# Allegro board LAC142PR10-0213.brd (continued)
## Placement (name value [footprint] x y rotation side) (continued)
CX26  3.3P_0402_50V8C  [C_0402]  18.6 71.45 270 bottom
CX27  3.3P_0402_50V8C  [C_0402]  18.6 64.95 90 bottom
CX28  3.3P_0402_50V8C  [C_0402]  18.6 64.08 270 bottom
CX29  3.3P_0402_50V8C  [C_0402]  18.6 61.26 90 bottom
CX30  3.3P_0402_50V8C  [C_0402]  18.6 60.4 270 bottom
CX49  4.7U_0805_10V4Z  [C_0805]  88.77 151.09 270 top
CX50  0.1U_0402_10V7K  [C_0402]  87.43 151.09 270 top
CX51  4.7U_0805_10V4Z  [C_0805]  83.84 154.13 180 top
CX52  0.1U_0402_10V7K  [C_0402]  85.17 155.55 0 top
CZ1  0.1U_0402_16V4Z  [C_0402]  37.14 64.97 270 top
CZ2  0.1U_0402_16V4Z  [C_0402]  37.27 73.96 90 top
CZ3  10U_0603_6.3V6M  [C_0603]  32.89 73.66 180 top
CZ4  0.1U_0402_16V4Z  [C_0402]  32.9 71.25 180 top
CZ5  0.1U_0402_16V4Z  [C_0402]  41.2 64.97 270 top
CZ6  0.1U_0402_16V4Z  [C_0402]  35.74 64.97 270 top
CZ7  2.2U_0402_6.3V6M  [C_0402]  42.14 67.18 0 top
CZ8  0.1U_0402_16V4Z  [C_0402]  42.14 66.29 0 top
CZ16  0.1U_0402_16V7K  [C_0402]  95.74 90.55 0 bottom
CZ17  0.1U_0402_16V7K  [C_0402]  95.74 89.66 0 bottom
CZ18  10P_0402_50V8J  [C_0402]  25.75 56.73 270 top
CZ19  10P_0402_50V8J  [C_0402]  25.74 58.85 270 top
CZ20  10P_0402_50V8J  [C_0402]  25.75 59.77 90 top
CZ21  10P_0402_50V8J  [C_0402]  23.96 55.86 0 top
CZ22  10P_0402_50V8J  [C_0402]  23.95 57.96 0 top
CZ23  10P_0402_50V8J  [C_0402]  23.98 60.63 0 top
CZ24  10U_0603_6.3V6M  [C_0603]  42.35 64.96 270 top
CZ25  0.1U_0402_16V7K  [C_0402]  88.53 98.17 180 bottom
CZ26  10U_0603_6.3V6M  [C_0603]  32.89 72.39 180 top
CZ27  10P_0402_50V8J  [C_0402]  27.59 55.84 90 top
CZ28  10P_0402_50V8J  [C_0402]  27.55 57.94 90 top
CZ29  10P_0402_50V8J  [C_0402]  27.52 60.68 270 top
CZ30  0.1U_0402_16V7K  [C_0402]  88.53 97.28 180 bottom
CZ31  0.1U_0402_16V7K  [C_0402]  90.73 96.01 180 bottom
CZ32  0.1U_0402_16V7K  [C_0402]  90.73 96.9 180 bottom
CZ33  10P_0402_50V8J  [C_0402]  36 76.44 90 top
CZ34  10P_0402_50V8J  [C_0402]  35.05 76.44 90 top
D3  RB751V-40 SOD-323  [RB751V-40TE17_SOD323-2]  114.07 111.89 90 top
D4  RB751V-40-H-GP  [RB751V-40_SOD323-2]  163.96 42.92 270 top
D20  -  [PESD24VS2UT_SOT23-3]  22.75 77.68 180 top
D31  -  [DB2J31400L_SOD323-2]  55.9 67.94 0 top
D32  -  [DB2J31400L_SOD323-2]  55.9 66.29 0 top
D101  BAS40C-2-GP  [BAS40-04_SOT23-3]  22.22 11.48 90 bottom
D5501  -  [RB551V-30_SOD323-2]  17.67 80.33 270 top
DA8  -  [BAT54C-7-F_SOT23-3]  180.87 24.07 270 bottom
DA13  AZ5125-02S.R7G_SOT23-3  [AZ5125-02SPR7G_SOT23-3]  84.61 9.02 270 top
DA14  AZ5125-02S.R7G_SOT23-3  [AZ5125-02SPR7G_SOT23-3]  84.61 4.32 270 top
DI1  IP4292CZ10-TBR_XSON10_2.5X1~D  [IP4292CZ10-TBR_XSON10_2P5X1]  18.81 37.61 90 bottom
DI2  -  [L30ESDL5V0C3-2_SOT23-3]  19.64 40 90 top
DI3  -  [L30ESDL5V0C3-2_SOT23-3]  189.06 42.42 90 top
DI4  -  [L30ESDL5V0C3-2_SOT23-3]  189.06 38.35 90 top
DX1  -  [RB751V-40_SOD323-2]  94.45 157.02 180 bottom
DX2  -  [PESD5V0U2BT_SOT23-3]  101.4 163.73 0 bottom
EC6104  SCD1U16V2KX-3GP  [C_0402]  26.79 2.69 0 top
FD1  FIDUCAL  [FIDUCIAL_C40M80]  14.24 163.51 0 top
FD2  FIDUCIAL  [FIDUCIAL_C40M80]  14.22 177.8 180 bottom
FD3  FIDUCAL  [FIDUCIAL_C40M80]  200.59 3.05 0 top
FD4  FIDUCIAL  [FIDUCIAL_C40M80]  200.59 3.05 180 bottom
FD5  FIDUCAL  [FIDUCIAL_C40M80]  187.55 23.32 0 top
FD6  FIDUCIAL  [FIDUCIAL_C40M80]  199.65 23 180 bottom
FE1  0.75A_24V_1812L075-24DR~OK  [F_1812L075-24DR]  193.46 130.68 0 top
FX1  1.5A_6V_1206L150PR~D  [F_1206L150PR]  15.67 78.28 90 top
H1  -  [H_3P0]  37.75 164.77 0 top
H2  -  [H_3P0]  20.65 50.77 0 top
H3  -  [H_3P0X3P8N]  6.15 79.07 90 top
H4  -  [H_3P0]  169.65 12.77 0 top
H5  -  [H_3P0]  154.25 60.97 0 top
H6  -  [H_3P2]  199.85 56.27 0 top
H7  -  [H_3P2]  142.05 165.77 0 top
H8  -  [H_4P0N]  148.45 163.97 0 top
H14  -  [H_3P0]  96.65 128.47 0 top
H21  -  [H_3P3]  146.05 150.37 0 top
H22  -  [H_3P3]  200.85 149.17 0 top
H23  -  [H_3P3]  174 112.42 0 top
H31  -  [H_3P4]  118.15 105.07 0 top
H32  -  [H_3P7]  90.95 70.77 0 top
H33  -  [H_3P7]  145.35 70.77 0 top
HDLED1  LED-W-27-GP-U  [LED_12-21C-T3D-CM2P1B18X-2C_3P]  24.45 1.46 0 top
J10  -  [JUMP_43X79]  151.19 129.58 270 top
J11  -  [JUMP_43X118]  151.95 135.72 90 top
J509  -  [JUMP_43X118]  35.74 15.83 90 top
J510  -  [JUMP_43X79]  40.32 15.83 90 top
J511  -  [JUMP_43X118]  30.54 15.83 90 top
JCRT  C-K_80461-5K1-152  [C-K_80461-5K1-152_15P-T-S]  13.8 60.89 90 bottom
JDIMM1  FOX_AS0A621-J4SB-7H  [FOX_AS0A621-J4SB-7H_204P]  88.5 24.97 0 bottom
JDIMM2  FOX_AS0A621-J4RB-7H  [FOX_AS0A621-J4RB-7H_204P]  80.3 38.17 180 bottom
JEDP  ACES-CON40-18-GP  [ACES_51540-04001-P01_40P-T]  80.8 165.93 0 bottom
JFAN  ACES_50224-0030N-001  [ACES_50224-0030N-001_3P-T]  92.46 136.72 25 bottom
JHDD1  ACES_51625-01201-001  [ACES_51625-01201-001_12P-T]  191.4 33.63 270 bottom
JHDD2  ACES_50208-01001-001  [ACES_50208-01001-001_10P]  202.05 27.28 90 bottom
JHDMI  C-K_96067-3K28-192-124  [C-K_96067-3K28-192-124_19P-T]  9.9 60.72 90 bottom
JHDT1  SAMTE_ASP-136446-07-B  [SAMTE_ASP-136446-07-B_20P-T]  48.82 72.64 270 top
JIO1  ACES_51524-0240N-001  [ACES_51524-0240N-001_24P]  191.85 21.76 90 top
JKB  ACES_51510-0304N-P01  [ACES_51510-0304N-P01_30P]  192.05 116.15 270 top
JKBBL  ACES_50524-00401-P01  [ACES_50524-00401-P01_4P]  192.05 121.57 90 top
JLAN  SDAN_601028-008041  [SANTA_130456-661_8P-T]  11.78 167.4 90 bottom
JNGFF  LCN_DAN05-67406-0100  [DAN05-67406-0100_67P-T]  163.37 63.03 270 bottom
JODD  AECS_51519-02001-001  [ACES_51519-02001-001_20P-T]  155.25 76.57 90 top
JP2  -  [JUMP_43X39]  190.42 143.43 0 bottom
JP3  2MM  [JUMP_43X39]  37.6 171.96 180 top
JP7  -  [JUMP_43X79]  153.77 89.66 180 top
JP12  -  [JUMP_43X39]  19.61 10.87 270 bottom
JP13  -  [JUMP_43X79]  189.6 39.58 90 bottom
JP14  -  [JUMP_43X39]  19.61 12.37 90 bottom
JP15  -  [JUMP_43X39]  39.5 74.68 180 top
JPWR  JXT_FP202DH-004M10M  [JXT_FP202DH-004M10M_4P]  197.15 167.79 0 top
JREAD  TAI_PSDATG-11GLBS1NN4H0  [TAI_PSDATG-11GLBS1NN4H0_11P-T]  25.38 10 270 top
JRTC  LOTES_AAA-BAT-054-K01  [LOTES_AAA-BAT-054-K01_2P]  27.15 14.61 180 bottom
JSPK  ACES_50224-0040N-001  [ACES_50224-0040N-001_4P-T]  77.97 5.57 90 bottom
JTP  JXT_FP202DH-008M10M  [JXT_FP202DH-008M10M_8P]  62.58 72.61 90 top
JUSB1  SUYIN_020053GR009M221ZL  [SUYIN_020053GR009M221ZL_9P-T]  14.82 43.47 90 bottom
L22  FBMA-L11-201209-121LMA50T_0805  [KC_FBMA-L11-201209-121LMA50_2P]  147.63 80.51 270 top
LA1  BLM15BB221SN1D_2P  [MURAT_BLM15BB221SN1D_2P]  178.16 9.66 180 bottom
LA3  NBQ160808T-800Y-N 0603  [R_0603]  91.18 5.59 180 top
LA4  NBQ160808T-800Y-N 0603  [R_0603]  91.18 3.3 180 top
LA5  NBQ160808T-800Y-N 0603  [R_0603]  91.18 9.65 180 top
LA6  NBQ160808T-800Y-N 0603  [R_0603]  91.18 7.37 180 top
LA7  0_0402_5%  [R_0402]  192.26 13.31 90 bottom
LA8  0_0603_5%  [R_0603]  191.62 17.4 0 bottom
LA9  0_0603_5%  [R_0603]  191.62 15.88 0 bottom
LA10  0_0402_5%  [R_0402]  189.78 20.65 180 bottom
LE3  FBMA-L11-160808-800LMT_0603  [KC_FBMA-L11-160808-800LMT_2P]  178.56 78.22 270 bottom
LE4  FBMA-L11-160808-800LMT_0603  [KC_FBMA-L11-160808-800LMT_2P]  182.29 82.68 180 top
LED1  LTW-327ZDSKS-5A 3X1 YELLOW/WHITE  [LED_12-22A-S2ST3D-C30-2C_3P]  16.55 2.17 180 top
LI1  S COM FI_ CHILISIN CMMI21T-670Y-N  [MURAT_DLW21SN670HQ2L_4P]  23.39 37.45 180 bottom
LI2  WCM-2012HS-900T_4P  [INPAQ_HCM2012GA900AE_4P]  22.44 41.52 180 top
LI3  S COM FI_ CHILISIN CMMI21T-670Y-N  [MURAT_DLW21SN670HQ2L_4P]  23.39 39.1 180 bottom
LI7  WCM-2012HS-900T_4P  [INPAQ_HCM2012GA900AE_4P]  183.23 42.75 0 top
LI8  WCM-2012HS-900T_4P  [INPAQ_HCM2012GA900AE_4P]  183.23 38.82 0 top
LL1  2.2UH_LQM2MPN2R2NG0L_30%  [MURAT_LQM2MPN2R2NG0L_2P]  55.43 172.12 270 top
LR2  WCM-2012HS-900T_4P  [INPAQ_HCM2012GA900AE_4P]  11.96 18.03 0 bottom
LV2  BLM15BD121SN1D_0402  [R_0402]  169.24 120.11 270 bottom
LV3  BLM15BD121SN1D_0402  [R_0402]  161.36 125.59 0 top
LV4  BLM15BD121SN1D_0402  [R_0402]  164.96 125.91 90 top
LV6  BLM15BB221SN1D_2P  [MURAT_BLM15BB221SN1D_2P]  177.41 136.27 180 top
LV7  BLM15BD121SN1D_0402  [R_0402]  184.61 138.91 180 top
LV8  BLM15BD121SN1D_0402  [R_0402]  184.56 139.91 180 top
LV25  BLM15BD121SN1D_0402  [R_0402]  171.32 134.76 270 top
LV26  BLM15BD121SN1D_0402  [R_0402]  172.2 134.77 270 top
LX1  FBMA-L11-201209-221LMA30T_0805  [KC_FBMA-L11-201209-221LMA30_2P]  83.52 157.77 180 bottom
LX2  WCM-2012HS-900T_4P  [INPAQ_HCM2012GA900AE_4P]  21.48 68.6 180 bottom
LX3  WCM-2012HS-900T_4P  [INPAQ_HCM2012GA900AE_4P]  21.48 72.28 180 bottom
LX4  WCM-2012HS-900T_4P  [INPAQ_HCM2012GA900AE_4P]  21.48 64.92 180 bottom
LX5  WCM-2012HS-900T_4P  [INPAQ_HCM2012GA900AE_4P]  21.48 61.23 180 bottom
LX6  WCM-2012HS-900T_4P  [INPAQ_HCM2012GA900AE_4P]  96.26 160.62 90 bottom
LZ1  SBY100505T-470Y-N_2P  [CHILI_SBY100505T-470Y-N_2P]  24.81 56.73 180 top
LZ2  SBY100505T-470Y-N_2P  [CHILI_SBY100505T-470Y-N_2P]  24.81 58.84 180 top
LZ3  SBY100505T-470Y-N_2P  [CHILI_SBY100505T-470Y-N_2P]  24.83 59.76 180 top
NOREF  -  []  20.65 50.77 0 top
NOREF#2  -  []  142.05 165.77 0 top
NOREF#3  -  []  200.85 149.17 0 top
NOREF#4  -  []  199.85 56.27 0 top
NOREF#5  -  []  37.75 164.77 0 top
NOREF#6  -  []  55.3 220.85 0 top
NOREF#7  -  []  145.35 70.77 0 top
NOREF#8  -  []  90.95 70.77 0 top
NOREF#9  -  []  174 112.42 0 top
NOREF#10  -  []  118.15 105.07 0 top
NOREF#11  -  []  46.26 15.06 0 top
NOREF#12  -  []  146.05 150.37 0 top
NOREF#13  -  []  114.31 8.25 0 top
NOREF#14  -  []  103.05 -41.53 0 top
NOREF#15  -  []  97.47 6.98 0 top
NOREF#16  -  []  134.04 6.67 0 top
NOREF#17  -  []  154.25 60.97 0 top
NOREF#18  -  []  96.65 128.47 0 top
NOREF#19  -  []  169.65 12.77 0 top
NOREF#20  -  []  121.9 61.57 180 bottom
NOREF#21  -  []  117.65 52.1 180 bottom
NOREF#22  -  []  80.94 70.52 180 bottom
PBATT1  SUYIN_200277GR008M270ZR  [SUYIN_200277GR008M270ZR_8P-T]  152.4 179.77 0 bottom
PC1  1000P_0402_50V7K  [C_0402]  83.64 158.08 270 top
PC2  100P_0402_50V8J  [C_0402]  82.75 158.08 270 top
PC3  1000P_0402_50V7K  [C_0402]  76.64 159.56 270 top
PC4  100P_0402_50V8J  [C_0402]  77.53 159.56 270 top
PC5  0.1U_0402_25V6  [C_0402]  141.92 154.19 270 top
PC6  0.1U_0402_25V6  [C_0402]  175.95 83.13 270 top
PC7  0.01U_0402_25V7K  [C_0402]  155.17 177.67 0 top
PC8  1000P_0402_50V7K  [C_0402]  158.12 177.67 180 top
PC13  .1U_0402_16V7K  [C_0402]  179.89 67.39 270 bottom
PC14  .1U_0402_16V7K  [C_0402]  146.36 170.89 270 top
PC15  0.01U_0402_25V7K  [C_0402]  149.99 168.15 180 top
PC16  .1U_0402_16V7K  [C_0402]  147.76 160.86 270 top
PC100  4.7U_0603_6.3V6K  [C_0603]  48.13 53.4 0 top
PC101  150U_D2_6.3VY_R15M  [C_D2]  29.27 31.73 90 bottom
PC102  100P_0402_50V8J  [C_0402]  39.86 54.23 0 top
PC103  680P_0402_50V7K  [C_0402]  34.59 44.07 0 bottom
PC104  0.1U_0603_25V7K  [C_0603]  38.22 51.18 180 top
PC105  1U_0603_25V6K  [C_0603]  41.29 47.27 180 top
PC106  1U_0603_10V6K  [C_0603]  42.39 47.27 0 top
PC107  150U_D2_6.3VY_R15M  [C_D2]  49.21 31.75 90 bottom
PC108  100P_0402_50V8J  [C_0402]  43.05 54.23 0 top
PC109  1U_0603_10V6K  [C_0603]  41.9 54.23 90 top
PC110  0.1U_0603_25V7K  [C_0603]  47.3 51.12 180 top
PC111  680P_0402_50V7K  [C_0402]  42.36 44.01 180 bottom
PC112  10U_0805_25V6K  [C_0805]  40.36 45.25 270 top
PC113  0.1U_0402_25V6  [C_0402]  39.04 44.94 270 top
PC114  2200P_0402_50V7K  [C_0402]  38.15 44.94 270 top
PC115  10U_0805_25V6K  [C_0805]  36.84 45.27 270 top
PC200  0.1U_0603_25V7K  [C_0603]  64.89 18.92 180 top
PC201  2200P_0402_50V7K  [C_0402]  70 25.15 180 bottom
PC202  0.1U_0402_10V7K  [C_0402]  57.28 21.97 180 top
PC203  0.1U_0402_10V7K  [C_0402]  57.28 22.86 180 top
PC204  1U_0603_10V6K  [C_0603]  59.75 16.45 90 top
PC205  10U_0805_6.3V6K  [C_0805]  65.08 24.64 0 top
PC206  10U_0805_25V6K  [C_0805]  70.39 22.86 180 bottom
PC207  680P_0402_50V7K  [C_0402]  74.67 13.92 270 bottom
PC208  0.1U_0402_25V6  [C_0402]  70 24.19 180 bottom
PC209  1U_0603_10V6K  [C_0603]  57.4 19.05 180 top
PC210  0.033U_0402_16V7K  [C_0402]  60.06 24.76 90 top
PC211  10U_0805_6.3V6K  [C_0805]  65.08 22.86 0 top
PC212  10U_0805_25V6K  [C_0805]  70.39 21.08 180 bottom
PC213  220U_D2_2VY_R15M  [C_D2]  76.41 24.76 180 top
PC214  220P_0402_25V8J  [C_0402]  58.22 24.76 0 top
PC301  0.1U_0402_16V7K  [C_0402]  134.54 148.65 0 bottom
PC302  0.1U_0402_25V6  [C_0402]  140.39 142.05 90 top
PC303  2200P_0402_50V7K  [C_0402]  141.34 142.05 90 top
PC304  10U_0805_25V6K  [C_0805]  144.52 141.41 90 top
PC305  0.1U_0603_25V7K  [C_0603]  141.28 148.65 180 top
PC306  1U_0603_10V6K  [C_0603]  139.88 147.38 0 top
PC307  220U_D2_2VY_R15M  [C_D2]  135.44 126.05 0 top
PC308  10U_0805_25V6K  [C_0805]  142.74 141.41 90 top
PC309  680P_0402_50V7K  [C_0402]  136.07 141.27 90 bottom
PC310  220U_D2_2VY_R15M  [C_D2]  135.03 123.32 0 bottom
PC401  0.1U_0402_16V7K  [C_0402]  32.7 3.89 270 top
PC402  1U_0402_6.3V6K  [C_0402]  195.83 132.6 270 bottom
PC403  4.7U_0603_6.3V6K  [C_0603]  32.76 7.75 180 top
PC404  0.01U_0402_25V7K  [C_0402]  42.3 5.21 180 top
PC405  22UF_0805_6.3V6M  [C_0805]  42.09 7.91 90 top
PC501  0.1U_0402_25V6K  [C_0402]  59.49 32.44 90 bottom
PC502  1U_0603_10V6K  [C_0603]  58.9 38.67 270 bottom
PC503  1U_0603_10V6K  [C_0603]  57.67 38.68 270 bottom
PC504  10U_0805_25V6K  [C_0805]  68.92 46.9 270 top
PC505  10U_0805_25V6K  [C_0805]  63.3 45.94 270 top
PC506  10U_0805_25V6K  [C_0805]  65.08 45.94 270 top
PC507  2200P_0402_50V7K  [C_0402]  72.07 46.18 270 top
PC508  0.1U_0402_25V6  [C_0402]  71.18 46.18 270 top
PC509  1000P_0402_50V7K  [C_0402]  61.27 33.35 270 bottom
PC510  0.22U_0603_25V7K  [C_0603]  61.97 40.39 180 top
PC511  680P_0603_50V7K  [C_0603]  72.89 46.1 270 bottom
PC512  1000P_0402_50V7K  [C_0402]  67.18 30.75 270 top
PC513  150P_0402_50V8J  [C_0402]  64.46 37.15 180 bottom
PC514  330P_0402_50V7K  [C_0402]  68.18 31.62 0 top
PC515  390P_0402_50V7K  [C_0402]  68.33 37.08 180 top
PC516  0.022U_0402_25V7K  [C_0402]  64.7 34.56 270 top
PC517  0.1U_0603_16V7K  [C_0603]  64.95 30.8 90 bottom
PC518  330P_0402_50V  [C_0402]  68.18 32.51 0 top
PC519  0.1U_0603_50V7K  [C_0603]  67.81 38.42 90 top
PC520  820P_0402_50V7K  [C_0402]  65.59 34.65 180 bottom
PC521  0.01U_0402_50V7K  [C_0402]  62.17 35.94 180 bottom
PC522  0.1U_0402_25V6  [C_0402]  70.29 46.18 270 top
PC523  1000P_0402_50V7K  [C_0402]  54.67 31.42 90 top
PC601  0.1U_0402_16V7K  [C_0402]  159.19 44.53 270 bottom
PC602  22UF_0805_6.3V6M  [C_0805]  156.86 40.64 180 bottom
PC603  68P_0402_50V8J  [C_0402]  158.3 40.06 90 bottom
PC604  22UF_0805_6.3V6M  [C_0805]  152.86 49.34 180 bottom
PC605  22UF_0805_6.3V6M  [C_0805]  152.86 47.56 180 bottom
PC606  680P_0402_50V7K  [C_0402]  154.41 43.69 0 bottom
PC705  2200P_0402_25V7K  [C_0402]  130.09 171.13 0 bottom
PC708  0.1U_0402_25V6  [C_0402]  121.12 173.43 270 bottom
PC711  0.01UF_0402_25V7K  [C_0402]  80.97 170.97 180 top
PC721  0.22U_0603_25V7K  [C_0603]  123.06 166.62 180 bottom
PC742  5600P_0402_25V7K  [C_0402]  78.52 164.47 180 top
PC744  0.1U_0402_25V6  [C_0402]  78.52 166.5 180 top
PC745  0.1U_0402_25V6  [C_0402]  112.5 163.58 0 top
PC746  0.1U_0402_25V6  [C_0402]  112.5 164.47 0 top
PC747  0.1U_0402_25V6  [C_0402]  114.86 165.31 0 top
PC748  2200P_0402_25V7K  [C_0402]  111.12 168.3 180 bottom
PC749  2200P_0402_25V7K  [C_0402]  110.2 169.19 0 bottom
PC750  0.22U_0603_25V7K  [C_0603]  117.94 163.64 270 bottom
PC751  560P_0402_50V7K  [C_0402]  112.14 173.42 270 bottom
PC752  0.015U_0402_25V7K  [C_0402]  112.17 174.29 0 bottom
PC753  10P_0402_50V8J  [C_0402]  116.61 173.41 270 bottom
PC757  1U_0603_25V6  [C_0603]  124.77 169.99 180 bottom
PC758  0.1U_0402_25V6  [C_0402]  121.12 171.64 0 bottom
PC759  0.1U_0402_25V6  [C_0402]  120.21 172.51 90 bottom
PC760  10U_0805_25V6K  [C_0805]  127.84 170.69 180 bottom
PC761  10U_0805_25V6K  [C_0805]  142.74 174.62 90 top
PC762  10U_0805_25V6K  [C_0805]  127.84 168.91 180 bottom
PC763  10U_0805_25V6K  [C_0805]  127.84 165.35 180 bottom
PC764  10U_0805_25V6K  [C_0805]  127.84 167.13 180 bottom
PC765  0.1U_0402_25V7K  [C_0402]  130.09 170.24 0 bottom
PC766  10U_0805_25V6K  [C_0805]  148.08 174.62 90 top
PC767  680P_0603_50V7K  [C_0603]  137.03 165.42 90 bottom
PC768  1U_0402_16V6K  [C_0402]  121.61 168.99 180 top
PC769  1U_0402_16V6K  [C_0402]  118.31 168.98 270 top
PC775  10U_0805_25V6K  [C_0805]  146.3 174.62 90 top
PC776  10U_0805_25V6K  [C_0805]  144.52 174.62 90 top
PC777  0.1U_0402_25V7K  [C_0402]  149.41 175.06 90 top
PC779  0.1U_0402_25V7K  [C_0402]  135.18 175.06 90 top
PC801  4.7U_0805_6.3V6K  [C_0805]  34.94 49.02 180 bottom
PC802  1U_0603_10V6K  [C_0603]  33.65 54.1 0 bottom
PC803  .1U_0402_16V7K  [C_0402]  29.51 46.35 0 bottom
PC804  10U_0603_6.3V6M  [C_0603]  27.17 47.37 180 bottom
PC805  .1U_0402_16V7K  [C_0402]  30.74 41.15 180 bottom
PC836  330U_D2_2V_Y  [C_D2]  195.76 120.24 90 bottom
PC837  330U_D2_2V_Y  [C_D2]  190.94 120.24 90 bottom
PC838  330U_D2_2V_Y  [C_D2]  186.11 120.24 90 bottom
PC839  330U_D2_2V_Y  [C_D2]  187.91 115.82 180 bottom
PC953  330U_D2_2V_Y  [C_D2]  118.19 128.52 180 top
PC954  330U_D2_2V_Y  [C_D2]  118.19 123.82 180 bottom
PC955  330U_D2_2V_Y  [C_D2]  118.19 123.82 180 top
PC956  330U_D2_2V_Y  [C_D2]  118.19 119.13 180 bottom
PC959  330U_D2_2V_Y  [C_D2]  128.71 125.35 180 bottom
PC960  330U_D2_2V_Y  [C_D2]  128.71 120.59 180 bottom
PC967  330U_D2_2V_Y  [C_D2]  67.43 65.53 180 bottom
PC968  330U_D2_2V_Y  [C_D2]  67.43 60.77 180 bottom
PC969  330U_D2_2V_Y  [C_D2]  71.94 60.43 90 bottom
PC1000  S ELE CAP 33U 25V  [C_VSS330M1ETR-0604]  109.15 132.49 90 bottom
PC1001  S ELE CAP 33U 25V  [C_VSS330M1ETR-0604]  103.88 152.53 0 bottom
PC1002  10U_0805_25V6K  [C_0805]  112.58 143.36 90 top
PC1003  10U_0805_25V6K  [C_0805]  110.86 143.36 90 top
PC1004  330P_0402_50V7K  [C_0402]  125.91 158.76 270 top
PC1005  S ELE CAP 33U 25V  [C_VSS330M1ETR-0604]  103.66 144.14 180 bottom
PC1006  390P_0402_50V7K  [C_0402]  124.99 156.06 180 top
PC1007  1000P_0402_50V7K  [C_0402]  123.15 158.76 0 top
PC1008  220P_0402_50V8J  [C_0402]  123.19 156.04 270 top
PC1009  0.22U_0603_25V7K  [C_0603]  124.88 154.07 180 top
PC1010  0.01U_0402_50V7K  [C_0402]  123.15 160.53 270 top
PC1011  0.022U_0402_25V7K  [C_0402]  123.16 161.54 270 bottom
PC1012  0.1U_0603_16V7K  [C_0603]  122.21 158.69 0 bottom
PC1013  680P_0603_50V7K  [C_0603]  132.67 139.36 90 bottom
PC1014  0.1U_0603_50V7K  [C_0603]  124.22 159.79 90 bottom
PC1015  220P_0402_50V7K  [C_0402]  123.53 156.71 180 bottom
PC1018  1000P_0402_50V7K  [C_0402]  120.23 156.4 90 bottom
PC1037  330P_0402_50V7K  [C_0402]  110.81 152.07 270 top
PC1038  0.22U_0603_25V7K  [C_0603]  117.69 148.36 90 top
PC1039  10U_0805_25V6K  [C_0805]  125.27 147 0 bottom
PC1053  0.1U_0603_16V7K  [C_0603]  113.85 159.83 270 top
PC1054  680P_0603_50V7K  [C_0603]  119.31 144.21 90 top
PC1055  1U_0603_10V6K  [C_0603]  121.28 149.7 270 top
PC1056  2200P_0402_50V7K  [C_0402]  125.84 148.35 0 top
PC1057  390P_0402_50V7K  [C_0402]  112.6 152.1 0 top
PC1058  0.01U_0402_50V7K  [C_0402]  109.03 152.12 180 top
PC1059  330P_0402_50V7K  [C_0402]  113.55 155.7 180 top
PC1060  1000P_0402_50V7K  [C_0402]  112.59 154.81 270 top
PC1061  820P_0402_50V7K  [C_0402]  112.62 156.62 0 top
PC1062  1000P_0402_50V7K  [C_0402]  116.77 156.39 90 bottom
PC1063  1U_0603_10V6K  [C_0603]  118.79 148.36 0 top
PC1064  0.1U_0402_25V6K  [C_0402]  118.5 157.31 270 bottom
PC1065  0.1U_0603_50V7K  [C_0603]  109.05 155.77 90 top
PC1066  0.022U_0402_25V7K  [C_0402]  110.8 157.29 270 top
PC1067  10U_0805_25V6K  [C_0805]  125.27 147 0 top
PC1068  150P_0402_50V8J  [C_0402]  112.6 153 0 top
PC1069  0.1U_0402_25V6K  [C_0402]  125.84 148.34 0 bottom
PC1070  10U_0805_25V6K  [C_0805]  114.29 143.36 90 top
PC1071  2200P_0402_50V7K  [C_0402]  108.48 143.27 90 top
PC1072  0.1U_0402_25V6K  [C_0402]  109.45 143.28 90 top
PC1101  0.1U_0402_25V6K  [C_0402]  167.18 92.39 0 top
PC1103  10U_0805_25V6K  [C_0805]  188.52 91.06 180 bottom
PC1104  10U_0805_25V6K  [C_0805]  169.6 105.7 90 top
PC1105  10U_0805_25V6K  [C_0805]  171.38 105.7 90 top
PC1106  2200P_0402_50V7K  [C_0402]  173.22 101.42 270 bottom
PC1107  0.1U_0402_25V6K  [C_0402]  187.59 92.39 180 bottom
PC1108  0.22U_0603_25V7K  [C_0603]  175.82 89.66 90 bottom
PC1109  680P_0603_50V7K  [C_0603]  188.97 106.49 0 bottom
PC1110  1U_0603_10V6K  [C_0603]  172.21 91.88 90 top
PC1111  1U_0603_10V6K  [C_0603]  172.21 90.93 270 top
PC1112  10U_0805_25V6K  [C_0805]  173.16 105.7 90 top
PC1113  10U_0805_25V6K  [C_0805]  188.52 87.5 180 bottom
PC1114  10U_0805_25V6K  [C_0805]  188.52 89.28 180 bottom
PC1115  2200P_0402_50V7K  [C_0402]  174.11 101.42 270 bottom
PC1116  0.1U_0402_25V6  [C_0402]  187.59 93.28 180 bottom
PC1117  1000P_0402_50V7K  [C_0402]  168.09 93.28 180 top
PC1118  0.22U_0603_25V7K  [C_0603]  175.82 94.17 270 bottom
PC1119  0.22U_0402_10V6K  [C_0402]  166.74 97.58 270 bottom
PC1120  0.22U_0402_10V6K  [C_0402]  167.63 97.58 270 bottom
PC1121  680P_0603_50V7K  [C_0603]  178.05 98.04 270 bottom
PC1122  1000P_0402_50V7K  [C_0402]  170.62 96.89 90 top
PC1123  270P_0402_50V7K  [C_0402]  172.13 96.65 0 bottom
PC1124  330P_0402_50V7K  [C_0402]  170.62 95.14 270 top
PC1125  0.033U_0402_16V7K  [C_0402]  169.42 97.59 180 bottom
PC1126  0.15U_0603_16V7K  [C_0603]  169.35 98.66 180 bottom
PC1127  390P_0402_50V7K  [C_0402]  173.03 98.41 270 bottom
PC1128  330P_0402_50V  [C_0402]  171.18 99.31 0 bottom
PC1129  0.1U_0603_50V7K  [C_0603]  169.35 95.31 270 top
PC1130  820P_0402_50V7K  [C_0402]  167.94 96.9 0 top
PC1131  0.01U_0402_50V7K  [C_0402]  171.51 95.14 270 top
PC1201  2.2U_0402_10V6M  [C_0402]  193.99 132.6 270 bottom
PC1202  1U_0402_6.3V6K  [C_0402]  32.7 6.43 270 top
PC1203  4.7U_0603_6.3V6K  [C_0603]  197.41 132.59 270 bottom
PC1204  0.01U_0402_25V7K  [C_0402]  194.56 142 270 bottom
PC1205  22UF_0805_6.3V6M  [C_0805]  200.12 142.75 0 bottom
PC1401  2200P_0402_50V7K  [C_0402]  192.87 168.03 180 bottom
PC1402  0.22U_0402_10V6K  [C_0402]  200.89 159.26 0 bottom
PC1403  680P_0603_50V7K  [C_0603]  192.14 162.61 0 bottom
PC1404  0.1U_0603_25V7K  [C_0603]  198.94 168.78 270 bottom
PC1405  0.1U_0402_25V6  [C_0402]  192.87 167.14 180 bottom
PC1406  10U_0805_25V6K  [C_0805]  193.82 164.11 180 bottom
PC1407  10U_0805_25V6K  [C_0805]  193.82 165.83 180 bottom
PC1408  330P_0402_50V7K  [C_0402]  200.15 163.18 90 bottom
PC1409  47U_0805_6.3V6M  [C_0805]  200.75 154.31 0 bottom
PC1410  47U_0805_6.3V6M  [C_0805]  194.07 156.97 180 bottom
PC1411  22UF_0805_6.3V6M  [C_0805]  200.75 156.08 0 bottom
PC1412  22UF_0805_6.3V6M  [C_0805]  194.07 155.19 180 bottom
PC1413  4.7U_0603_6.3V6K  [C_0603]  200.46 169.74 90 bottom
PC1414  4.7U_0603_6.3V6K  [C_0603]  196.94 169.94 0 bottom
PD2  -  [TVNST52302AB0_SOT523-3]  161.35 173.67 0 bottom
PD3  -  [TVNST52302AB0_SOT523-3]  157.92 173.67 0 bottom
PD101  -  [TVNST52302AB0_SOT523-3]  46.79 54.17 270 top
PD704  -  [SDMK0340L-7-F_SOD323-2]  120.74 163.66 180 top
PD705  -  [SDMK0340L-7-F_SOD323-2]  120.73 165.37 180 top
PD706  -  [SDMK0340L-7-F_SOD323-2]  78.73 169.13 90 top
PH1  100K_0402_1%_TSM0B104F4251RZ  [R_0402]  105.01 78.49 0 top
PH501  470K_0402_5%_TSM0B474J4702RE  [R_0402]  62.16 29.9 90 bottom
PH502  10K_0402_5%_ERTJ0ER103J  [R_0402]  74.29 57.42 270 bottom
PH1000  10K_0402_5%_ERTJ0ER103J  [R_0402]  129.6 134.8 90 bottom
PH1001  470K_0402_5%_TSM0B474J4702RE  [R_0402]  126.74 149.26 180 bottom
PH1002  470K_0402_5%_TSM0B474J4702RE  [R_0402]  112.78 136.52 180 top
PH1003  10K_0402_5%_ERTJ0ER103J  [R_0402]  111.79 134.96 270 bottom
PH1101  470K_0402_5%_TSM0B474J4702RE  [R_0402]  171.84 101.47 180 bottom
PH1102  10K_0402_5%_ERTJ0ER103J  [R_0402]  179.71 112.65 180 bottom
PJP1  JUMP_43X79  [JUMP_43X79-NPM]  80.76 160.46 0 top
PJP2  JUMP_43X79  [JUMP_43X79-NPM]  97.57 156.93 90 top
PJP3  JUMP_43X79  [JUMP_43X79-NPM]  157.2 175.26 180 top
PJP100  PAD-OPEN 4x4m  [JUMP_43X118]  34.85 28.24 270 bottom
PJP101  PAD-OPEN 4x4m  [JUMP_43X118]  48.95 28.24 270 bottom
PJP102  PAD-OPEN 4x4m  [JUMP_43X118]  29.65 28.24 270 bottom
PJP103  PAD-OPEN 4x4m  [JUMP_43X118]  43.74 28.24 270 bottom
PJP104  JUMP_43X118  [JUMP_43X118-NPM]  48.95 44.43 270 top
PJP200  -  [JUMP_43X118]  79.77 24.76 0 top
PJP201  -  [JUMP_43X118]  79.77 19.56 0 top
PJP203  -  [JUMP_43X79]  62.54 26.2 270 top
PJP204  JUMP_43X79  [JUMP_43X79-NPM]  72.26 31.2 90 bottom
PJP301  -  [JUMP_43X118]  136.07 122.17 270 top
PJP302  -  [JUMP_43X118]  141.41 122.17 270 top
PJP303  JUMP_43X79  [JUMP_43X79-NPM]  137.98 138.26 90 top
PJP401  -  [JUMP_43X79]  33.58 10.84 270 top
PJP402  -  [JUMP_43X79]  44.59 7.87 0 top
PJP501  JUMP_43X79  [JUMP_43X79-NPM]  69.27 51.58 270 top
PJP601  -  [JUMP_43X79]  156.52 37.42 90 bottom
PJP602  -  [JUMP_43X79]  153.6 51.39 90 bottom
PJP701  JUMP_43X118  [JUMP_43X118-NPM]  128.71 159.85 90 bottom
PJP801  -  [JUMP_43X79]  33.58 52.24 270 bottom
PJP802  -  [JUMP_43X79]  26.85 44.54 90 bottom
PJP1001  JUMP_43X79  [JUMP_43X79-NPM]  102.88 157.99 0 bottom
PJP1101  JUMP_43X79  [JUMP_43X79-NPM]  165.11 109.09 0 top
PJP1201  -  [JUMP_43X79]  199.43 136.97 180 top
PJP1202  -  [JUMP_43X79]  195.3 144.4 180 bottom
PJP1401  -  [JUMP_43X118]  194.28 152.95 270 bottom
PJP1402  -  [JUMP_43X39]  197.59 172.43 270 bottom
PJP1403  JUMP_43X79  [JUMP_43X79-NPM]  194.49 169.6 90 bottom
PJPDC1  ACES_50458-00601-001  [ACES_50458-00601-001_6P-T]  98.15 161.74 180 top
PL1  FBMJ4516HS720NT_2P  [MURAT_BLM41PG600SN1L_2P]  83.22 160.46 180 top
PL2  BLM15AG102SN1D_2P  [MURAT_BLM15AG102SN1D_2P]  93.27 159.83 0 top
PL3  FBMJ4516HS720NT_2P  [MURAT_BLM41PG600SN1L_2P]  154.67 175.26 0 top
PL4  FBMJ4516HS720NT_2P  [MURAT_BLM41PG600SN1L_2P]  97.57 159.33 270 top
PL100  2.2UH_7.8A_20%_7X7X3_M  [L_7X7X3_M_2P]  35.24 37.57 270 bottom
PL101  2.2UH_7.8A_20%_7X7X3_M  [L_7X7X3_M_2P]  43.36 37.57 270 bottom
PL102  FBMJ4516HS720NT_2P  [MURAT_BLM41PG600SN1L_2P]  48.95 45.99 270 top
PL200  1UH_11A_20%_7X7X3_M  [L_7X7X3_M_2P]  78.16 22.2 270 bottom
PL201  FBMJ4516HS720NT_2P  [MURAT_BLM41PG600SN1L_2P]  72.26 33.73 270 bottom
PL301  FBMJ4516HS720NT_2P  [MURAT_BLM41PG600SN1L_2P]  137.98 140.79 270 top
PL302  1UH_PCMB104T-1R0MH_18A_20%  [CYNTE_PCMB104T-1R0MH_2P]  141.18 131.44 180 bottom
PL501  FBMJ4516HS720NT_2P  [MURAT_BLM41PG600SN1L_2P]  69.27 49.05 90 top
PL502  0.22UH_24A_20%_7X7X4_MOLDING  [TOKO_FDUM0640J-H-R36M-P3_4P]  62.99 54.48 0 bottom
PL601  1UH_2.8A_30%_4X4X2_M  [TAIYO_NRS4018T1R0NDGJ_2P]  155.63 46.61 90 bottom
PL700  4.7UH_5.5A_20%_7X7X3_M  [L_7X7X3_M_2P]  135.44 160.95 270 bottom
PL704  1UH_PCMB053T-1R0MS_7A_20%  [L_5X5X3_M_2P]  128.71 158.23 90 bottom
PL1001  FBMJ4516HS720NT_2P  [MURAT_BLM41PG600SN1L_2P]  105.41 157.99 180 bottom
PL1002  0.22UH_24A_20%_7X7X4_MOLDING  [TOKO_FDUM0640J-H-R36M-P3_4P]  125.28 138.11 270 bottom
PL1004  0.22UH_24A_20%_7X7X4_MOLDING  [TOKO_FDUM0640J-H-R36M-P3_4P]  116.52 136.59 270 bottom
PL1101  FBMJ4516HS720NT_2P  [MURAT_BLM41PG600SN1L_2P]  167.64 109.09 180 top
PL1102  0.22UH_24A_20%_7X7X4_MOLDING  [TOKO_FDUM0640J-H-R36M-P3_4P]  193.86 107.76 90 bottom
PL1103  0.22UH_24A_20%_7X7X4_MOLDING  [TOKO_FDUM0640J-H-R36M-P3_4P]  179.7 109.6 0 bottom
PL1401  FBMJ4516HS720NT_2P  [MURAT_BLM41PG600SN1L_2P]  194.49 172.03 270 bottom
PL1402  0.68UH_7.9A_20%_5X5X3_M  [CYNTE_PCMB053T-1R0MS_2P]  197.35 160.34 270 bottom
PQ1  L2N7002DW1T1G_SC88-6  [2N7002DW-T-R7_SOT363-6]  140.38 155.79 0 top
PQ2  L2N7002DW1T1G_SC88-6  [2N7002DW-T-R7_SOT363-6]  146.33 159.24 90 top
PQ3  L2N7002DW1T1G_SC88-6  [2N7002DW-T-R7_SOT363-6]  149.51 169.4 90 top
PQ4  L2N7002DW1T1G_SC88-6  [2N7002DW-T-R7_SOT363-6]  186.93 67.64 270 bottom
PQ5  MMST3904-7-F_SOT323  [RHU002N06_SOT323-3]  90.16 155.7 0 top
PQ6  FDV301N_G 1N SOT23-3  [FDV301N_NL_SOT23-3]  93.59 157.73 180 top
PQ101  MDV1528URH-1N-PDFN33-8  [SIS412DN-T1-GE3_POWERPAK8-5]  33.08 42.29 0 top
PQ102  FDMC7692S-1N-MLP  [SIS412DN-T1-GE3_POWERPAK8-5]  36.51 38.73 90 top
PQ103  MDV1528URH-1N-PDFN33-8  [SIS412DN-T1-GE3_POWERPAK8-5]  42.16 42.23 0 top
PQ104  FDMC7692S-1N-MLP  [SIS412DN-T1-GE3_POWERPAK8-5]  41.01 40.64 270 top
PQ200  MDV1528URH-1N-PDFN33-8  [SIS412DN-T1-GE3_POWERPAK8-5]  73.77 19.27 180 bottom
PQ201  FDMC7692S-1N-MLP  [SIS412DN-T1-GE3_POWERPAK8-5]  71.14 15.27 90 bottom
PQ301  AON6552_DFN5X6-8-5  [SIR472DP-T1-GE3_POWERPAK8-5]  140.77 134.49 0 top
PQ302  AON6554_DFN5X6-8-5  [SIR472DP-T1-GE3_POWERPAK8-5]  142.68 142.88 0 bottom
PQ501  AON6552_DFN5X6-8-5  [SIR472DP-T1-GE3_POWERPAK8-5]  61.14 51.18 270 top
PQ502  AON6554_DFN5X6-8-5  [SIR472DP-T1-GE3_POWERPAK8-5]  70.99 44.51 180 bottom
PQ503  AON6554_DFN5X6-8-5  [SIR472DP-T1-GE3_POWERPAK8-5]  65.02 44.51 180 bottom
PQ504  2N7002W-T/R7_SOT323-3  [SSM3K7002FU_SC70-3]  53.02 30.17 0 top
PQ704  AON7408L_DFN8-5  [SIS412DN-T1-GE3_POWERPAK8-5]  131.98 167.41 270 bottom
PQ707  L2N7002DW1T1G_SC88-6  [2N7002DW-T-R7_SOT363-6]  69.82 165.65 180 top
PQ708  AON7506_DFN33-8-5  [SIS412DN-T1-GE3_POWERPAK8-5]  133.53 168.53 0 bottom
PQ709  L2N7002DW1T1G_SC88-6  [2N7002DW-T-R7_SOT363-6]  82.47 167.78 180 top
PQ710  LMUN5113T1G PNP SOT323-3  [DTA144EUA_SC70-3]  108.38 167.64 270 top
PQ711  LMUN5236T1G NPN SOT323-3  [DTC115EUA_SC70-3]  109.18 165.37 180 top
PQ717  AON6414AL_DFN8-5  [SIR472DP-T1-GE3_POWERPAK8-5]  133.66 172.21 90 top
PQ718  AON6414AL_DFN8-5  [SIR472DP-T1-GE3_POWERPAK8-5]  72 170.01 0 top
PQ740  AON7426_DFN3X3EP8-5  [SIS412DN-T1-GE3_POWERPAK8-5]  75.82 165.84 180 top
PQ801  2N7002W-T/R7_SOT323-3  [SSM3K7002FU_SC70-3]  30.03 44.26 0 bottom
PQ1001  -  [AON6970_DFN5X6D-8-7]  123.95 141.48 90 bottom
PQ1007  AON6552_DFN5X6-8-5  [SIR472DP-T1-GE3_POWERPAK8-5]  117.4 137.99 90 top
PQ1008  AON6554_DFN5X6-8-5  [SIR472DP-T1-GE3_POWERPAK8-5]  112.2 144.66 0 bottom
PQ1009  AON6554_DFN5X6-8-5  [SIR472DP-T1-GE3_POWERPAK8-5]  118.04 144.66 0 bottom
PQ1101  AON6552_DFN5X6-8-5  [SIR472DP-T1-GE3_POWERPAK8-5]  195.39 91.06 270 bottom
PQ1102  AON6554_DFN5X6-8-5  [SIR472DP-T1-GE3_POWERPAK8-5]  190.05 93.22 90 bottom
PQ1103  AON6554_DFN5X6-8-5  [SIR472DP-T1-GE3_POWERPAK8-5]  190.05 99.06 90 bottom
PQ1104  AON6552_DFN5X6-8-5  [SIR472DP-T1-GE3_POWERPAK8-5]  176.59 106.62 270 bottom
PQ1105  AON6554_DFN5X6-8-5  [SIR472DP-T1-GE3_POWERPAK8-5]  187.89 99.56 180 bottom
PQ1106  AON6554_DFN5X6-8-5  [SIR472DP-T1-GE3_POWERPAK8-5]  182.05 99.56 180 bottom
PR1  200K_0402_1%  [R_0402]  140.14 153.28 90 top
PR2  10K_0402_1%  [R_0402]  141.03 154.19 270 top
PR3  2.2K_0402_5%  [R_0402]  93.21 153.92 180 top
PR4  33_0402_5%  [R_0402]  94.99 153.92 180 top
PR5  3.3K_1206_5%  [R_1206]  143.69 157.92 270 top
PR6  100K_0402_1%  [R_0402]  91.18 158.62 0 top
PR7  1M_0402_1%  [R_0402]  141.28 158.93 90 top
PR8  10K_0402_1%  [R_0402]  90.04 154.43 0 top
PR9  15K_0402_1%  [R_0402]  89.27 158.62 0 top
PR10  1M_0402_1%  [R_0402]  140.39 159.84 270 top
PR15  200_0402_5%  [R_0402]  156.51 176.09 0 bottom
PR16  10K_0402_1%  [R_0402]  150.55 159.94 90 top
PR18  100_0402_5%  [R_0402]  162.69 176.02 180 bottom
PR20  100_0402_5%  [R_0402]  160 176.02 0 bottom
PR23  100K_0402_1%  [R_0402]  182.56 67.39 270 bottom
PR24  14K_0402_1%  [R_0402]  184.21 61.29 270 top
PR26  887K_0402_1%  [R_0402]  180.78 67.39 270 bottom
PR27  383K_0402_1%  [R_0402]  181.67 67.39 270 bottom
PR28  10K_0402_1%  [R_0402]  149.61 160.85 180 top
PR29  100K_0402_1%  [R_0402]  148.7 159.96 0 top
PR30  160K_0402_1%  [R_0402]  149.08 167.26 0 top
PR31  1M_0402_1%  [R_0402]  143.14 159.89 180 top
PR32  100K_0402_1%  [R_0402]  145.48 169.99 180 top
PR33  1M_0402_1%  [R_0402]  142.22 160.78 0 top
PR34  80.6K_0402_1%  [R_0402]  177.73 83.13 270 top
PR35  10K_0402_1%  [R_0402]  176.84 83.13 270 top
PR36  0_0402_5%  [R_0402]  178.62 83.13 270 top
PR37  10K_0402_1%  [R_0402]  144.57 170.88 0 top
PR38  187K_0402_1%  [R_0402]  188.81 66.83 270 bottom
PR100  0_0402_5%  [R0402_0OHM]  38.61 53.34 180 top
PR101  0_0402_5%  [R0402_0OHM]  45.38 52.32 0 top
PR102  2.2K_0402_5%  [R_0402]  49.03 52.32 180 top
PR103  2.2_0603_5%  [R_0603]  36.82 49.91 0 top
PR104  15K_0402_1%  [R_0402]  43.05 55.12 0 top
PR105  130K_0402_1%  [R_0402]  42.86 52.72 270 bottom
PR106  10K_0402_1%  [R_0402]  41.97 52.72 270 bottom
PR107  10K_0402_1%  [R_0402]  41.08 51.8 90 bottom
PR108  100K_0402_1%  [R_0402]  40.19 52.72 270 bottom
PR109  6.49K_0402_1%  [R_0402]  39.86 55.12 0 top
PR110  20K_0402_1%  [R_0402]  47.17 52.31 90 top
PR111  2.2_0603_5%  [R_0603]  45.9 49.85 0 top
PR112  4.7_1206_5%  [R_1206]  42.92 40.2 90 bottom
PR113  4.7_1206_5%  [R_1206]  34.03 40.26 90 bottom
PR114  200_0402_5%  [R_0402]  43.74 51.64 270 bottom
PR115  10K_0402_5%  [R_0402]  37.7 52.45 0 top
PR200  0_0603_5%  [R0603_0OHM]  64.83 20 90 top
PR201  0_0402_5%  [R0402_0OHM]  56.37 21.08 0 top
PR202  0_0402_5%  [R0402_0OHM]  56.37 23.75 0 top
PR203  4.7_1206_5%  [R_1206]  73.46 13.33 180 bottom
PR204  68.1K_0402_1%  [R_0402]  57.33 25.65 270 top
PR205  10.2K_0402_1%  [R_0402]  60.89 16.94 90 top
PR206  5.1_0603_5%  [R_0603]  57.21 16.45 90 top
PR207  54.9K_0402_1%  [R_0402]  58.22 25.65 0 top
PR208  887K_0402_1%  [R_0402]  56.37 20.19 0 top
PR210  2.2_0603_5%  [R_0603]  58.48 17.84 270 top
PR301  0_0402_5%  [R0402_0OHM]  132.19 148.91 0 top
PR302  100K_0402_5%  [R_0402]  132.19 149.8 0 top
PR303  0_0603_5%  [R0603_0OHM]  139.88 149.92 0 top
PR304  42.2K_0402_1%  [R_0402]  135.45 149.54 180 bottom
PR305  4.7_1206_5%  [R_1206]  135.57 137.48 90 bottom
PR306  470K_0402_1%  [R_0402]  134.54 146.88 0 bottom
PR307  3.48K_0402_1%  [R_0402]  133.1 148.02 180 top
PR308  10K_0402_1%  [R_0402]  134.54 147.76 0 bottom
PR401  42.2K_0402_1%  [R_0402]  30.92 2.97 90 top
PR402  1.58K_0402_1%  [R_0402]  42.3 4.32 180 top
PR403  20K_0402_1%  [R_0402]  31.81 3.89 270 top
PR404  1.74K_0402_1%  [R_0402]  41.38 3.43 0 top
PR501  100K_0402_1%  [R_0402]  57.71 33.35 270 bottom
PR502  10K_0402_1%  [R_0402]  57.54 35.43 180 bottom
PR503  10K_0402_1%  [R_0402]  57.54 36.32 180 bottom
PR504  100K_0402_1%  [R_0402]  58.6 33.35 270 bottom
PR505  100K_0402_1%  [R_0402]  58.48 29.71 90 top
PR506  0_0402_5%  [R0402_0OHM]  59.49 29.9 90 bottom
PR507  1_0603_5%  [R_0603]  59.56 40.39 180 top
PR508  0_0402_5%  [R_0402]  60.38 29.9 90 bottom
PR509  0_0402_5%  [R0402_0OHM]  60.76 29.77 90 top
PR510  133K_0402_1%  [R_0402]  60.38 33.35 270 bottom
PR511  100K_0402_1%  [R_0402]  64.2 37.85 180 top
PR512  150K_0402_1%  [R_0402]  62.16 33.35 270 bottom
PR513  13.3K_0402_1%  [R_0402]  62.15 30.8 0 top
PR514  0_0603_5%  [R0603_0OHM]  63.05 39.12 90 top
PR515  10K_0402_1%  [R_0402]  63.81 31.86 90 top
PR516  4.7_1206_5%  [R_1206]  72.89 50.04 270 bottom
PR517  3.65K_0603_1%  [R_0603]  65.46 38.42 90 top
PR518  1_0402_1%  [R_0402]  66.73 38.4 90 top
PR519  301_0402_1%  [R_0402]  66.29 29.83 90 top
PR520  32.4K_0402_1%  [R_0402]  62.17 37.15 180 bottom
PR521  1.62K_0402_1%  [R_0402]  67.19 31.62 180 top
PR522  137K_0402_1%  [R_0402]  67.42 36.19 0 top
PR523  2.61K_0402_1%  [R_0402]  66.02 30.8 0 bottom
PR524  11K_0402_1%  [R_0402]  63.81 34.56 270 top
PR525  2K_0402_1%  [R_0402]  66.27 32.51 0 top
PR526  619_0402_1%  [R_0402]  63.81 33.71 90 bottom
PR527  10_0402_5%  [R_0402]  69.97 30.72 90 top
PR528  100_0402_1%  [R_0402]  64.67 33.72 0 bottom
PR529  0_0402_5%  [R0402_0OHM]  68.18 30.73 0 top
PR530  0_0402_5%  [R0402_0OHM]  63.54 35.94 0 bottom
PR531  10_0402_5%  [R_0402]  63.11 30.81 270 bottom
PR532  47K_0402_1%  [R_0402]  59.87 30.68 270 top
PR533  10K_0402_1%  [R_0402]  54.67 29.64 90 top
PR601  0_0402_5%  [R0402_0OHM]  160.08 44.53 270 bottom
PR602  1M_0402_5%  [R_0402]  159.18 45.47 0 bottom
PR603  4.7_0603_5%  [R_0603]  155.31 44.83 180 bottom
PR604  20K_0402_1%  [R_0402]  159.19 40.06 90 bottom
PR605  10K_0402_1%  [R_0402]  159.19 41.83 90 bottom
PR703  0.01_1206_1%  [R_1206_4P]  108.96 176.97 0 bottom
PR721  3.3K_1206_5%  [R_1206]  71.96 162.94 90 top
PR722  3.3K_1206_5%  [R_1206]  125.3 172.77 90 bottom
PR727  1K_0402_1%  [R_0402]  112.89 170.08 180 bottom
PR729  287K_0402_1%  [R_0402]  80.13 169.11 90 top
PR731  158K_0402_1%  [R_0402]  114.28 163.58 0 bottom
PR732  49.9K_0402_1%  [R_0402]  80.05 171.86 0 top
PR737  3M_0402_5%  [R_0402]  82.71 169.23 180 top
PR738  1M_0402_1%  [R_0402]  81.79 170.12 0 top
PR739  1M_0402_1%  [R_0402]  81.82 163.36 180 top
PR740  2_0402_5%  [R_0402]  112.5 165.35 0 top
PR741  100K_0402_1%  [R_0402]  112.5 163.58 0 bottom
PR742  2_0402_5%  [R_0402]  122.02 172.51 90 bottom
PR743  10_1206_5%  [R_1206]  121.86 168.34 0 bottom
PR744  1M_0402_1%  [R_0402]  80.03 164.31 270 top
PR745  100_0402_1%  [R_0402]  119.09 163.47 270 bottom
PR746  1M_0402_1%  [R_0402]  80.91 164.33 0 top
PR749  200K_0402_1%  [R_0402]  122.91 172.51 90 bottom
PR750  200K_0402_1%  [R_0402]  113.97 172.51 90 bottom
PR751  95.3K_0402_1%  [R_0402]  123.82 173.43 270 bottom
PR752  127K_0402_1%  [R_0402]  114.86 173.42 270 bottom
PR753  147K_0402_1%  [R_0402]  111.98 170.97 0 bottom
PR754  499_0402_1%  [R_0402]  113.07 173.42 270 bottom
PR755  66.5_0402_1%  [R_0402]  115.74 173.42 270 bottom
PR756  10K_0402_1%  [R_0402]  118.42 172.5 90 bottom
PR757  100K_0402_1%  [R_0402]  122.43 169.81 180 bottom
PR760  4.7_0402_5%  [R_0402]  119.2 168.98 270 top
PR761  0_0603_5%  [R0603_0OHM]  132.14 162.69 90 bottom
PR762  4.02K_0402_1%  [R_0402]  82.76 164.33 0 top
PR763  4.02K_0402_1%  [R_0402]  83.6 169.15 90 top
PR764  10K_0402_1%  [R_0402]  117.49 173.37 270 bottom
PR765  0.01_1206_1%  [R_1206_4P]  136.2 174.24 0 top
PR766  4.7_1206_5%  [R_1206]  134.36 163.89 0 bottom
PR769  0_0402_5%  [R0402_0OHM]  111.99 165.61 0 bottom
PR770  0_0402_5%  [R0402_0OHM]  111.98 166.52 0 bottom
PR771  0_0603_5%  [R0603_0OHM]  121.66 165.23 0 bottom
PR772  0_0402_5%  [R0402_0OHM]  112.5 162.69 0 top
PR773  0_0603_5%  [R_0603]  136.65 177.04 180 top
PR774  0_0402_5%  [R0402_0OHM]  111.98 168.3 0 bottom
PR775  0_0402_5%  [R0402_0OHM]  111.98 169.19 0 bottom
PR776  0_0402_5%  [R0402_0OHM]  119.33 172.51 90 bottom
PR777  0_0402_5%  [R0402_0OHM]  111.98 167.41 0 bottom
PR778  0_0402_5%  [R0402_0OHM]  77.6 165.48 0 top
PR779  0_0402_5%  [R_0402]  132.02 168.85 180 bottom
PR780  0_0603_5%  [R_0603]  108.77 169.72 0 top
PR781  0_0603_5%  [R0603_0OHM]  109.65 162.31 180 top
PR801  0_0402_5%  [R0402_0OHM]  29.83 40.26 0 bottom
PR802  3.24K_0402_1%  [R_0402]  30.42 47.24 180 bottom
PR803  1K_0402_1%  [R_0402]  29.51 45.47 0 bottom
PR1000  2K_0402_1%  [R_0402]  125 157.85 180 top
PR1002  10_0402_5%  [R_0402]  124.06 161.4 180 top
PR1003  1.5K_0402_1%  [R_0402]  124.94 159.66 270 top
PR1004  137K_0402_1%  [R_0402]  124.09 156.95 0 top
PR1005  41.2K_0402_1%  [R_0402]  124.08 155.15 0 top
PR1006  0_0402_5%  [R0402_0OHM]  124.01 160.54 270 top
PR1007  301_0402_1%  [R_0402]  123.2 157.86 270 top
PR1008  0_0603_5%  [R0603_0OHM]  123.51 152.71 0 top
PR1009  2.61K_0402_1%  [R_0402]  123.13 162.43 180 bottom
PR1010  4.7_1206_5%  [R_1206]  129.86 137.85 0 bottom
PR1011  11K_0402_1%  [R_0402]  122.16 159.72 0 bottom
PR1012  3.65K_0603_1%  [R_0603]  123.95 155.64 0 bottom
PR1013  301_0402_1%  [R_0402]  123.53 157.62 180 bottom
PR1014  1_0402_1%  [R_0402]  125.36 157.62 270 bottom
PR1015  100_0402_1%  [R_0402]  124.43 157.62 270 bottom
PR1016  13.3K_0402_1%  [R_0402]  120.95 159.65 180 top
PR1018  133K_0402_1%  [R_0402]  119.37 156.4 90 bottom
PR1021  100K_0402_1%  [R_0402]  119.16 160.2 270 top
PR1023  0_0402_5%  [R0402_0OHM]  118.28 160.2 270 top
PR1026  1_0603_5%  [R_0603]  118.79 149.59 0 top
PR1028  0_0402_5%  [R_0402]  118.28 160.2 270 bottom
PR1047  1.62K_0402_1%  [R_0402]  113.51 154.81 270 top
PR1051  10_0402_5%  [R_0402]  107.99 155.64 90 top
PR1065  2K_0402_1%  [R_0402]  111.7 152.97 180 top
PR1066  619_0402_1%  [R_0402]  112.62 157.48 0 top
PR1067  10_0402_5%  [R_0402]  108.26 153.9 270 top
PR1068  1_0402_1%  [R_0402]  108.01 153.87 270 bottom
PR1069  0_0402_5%  [R0402_0OHM]  109.9 152.09 90 top
PR1070  100K_0402_5%  [R_0402]  112.63 149.86 0 top
PR1071  11K_0402_1%  [R_0402]  112.77 159.32 270 top
PR1072  100_0402_1%  [R_0402]  111.69 157.29 270 top
PR1073  301_0402_1%  [R_0402]  111.69 153.87 180 top
PR1074  4.7_1206_5%  [R_1206]  119.31 140.27 90 top
PR1075  0_0402_5%  [R0402_0OHM]  111.69 154.79 180 top
PR1076  133K_0402_1%  [R_0402]  117.64 156.4 90 bottom
PR1077  137K_0402_1%  [R_0402]  111.73 152.09 270 top
PR1078  32.4K_0402_1%  [R_0402]  113.52 151.19 180 top
PR1079  2.61K_0402_1%  [R_0402]  111.69 158.18 180 top
PR1080  13.3K_0402_1%  [R_0402]  115.59 159.28 0 top
PR1081  10K_0402_1%  [R_0402]  116.85 155.49 180 bottom
PR1082  0_0603_5%  [R0603_0OHM]  116.42 149.73 270 top
PR1084  3.65K_0603_1%  [R_0603]  109.15 153.86 270 bottom
PR1085  0_0402_5%  [R0402_0OHM]  117.37 160.2 270 top
PR1086  150K_0402_1%  [R_0402]  120.03 160.53 0 top
PR1087  150K_0402_1%  [R_0402]  116.49 160.17 180 top
PR1101  100K_0402_1%  [R_0402]  169.93 89.73 180 top
PR1103  0_0603_5%  [R0603_0OHM]  174.49 88.46 0 bottom
PR1104  10K_0402_1%  [R_0402]  167.57 100.63 90 bottom
PR1105  10K_0402_1%  [R_0402]  169.84 87.76 0 bottom
PR1106  10K_0402_1%  [R_0402]  172.54 87.76 180 bottom
PR1107  4.7_1206_5%  [R_1206]  192.14 104.84 180 bottom
PR1108  3.65K_0603_1%  [R_0603]  166.43 100.14 90 bottom
PR1110  1_0402_1%  [R_0402]  165.28 100.63 90 bottom
PR1111  100K_0402_1%  [R_0402]  167.82 91.2 270 top
PR1112  100K_0402_1%  [R_0402]  164.51 91.06 0 bottom
PR1113  0_0402_5%  [R_0402]  164.51 92.84 0 bottom
PR1114  1_0603_5%  [R_0603]  173.41 92.46 270 top
PR1115  0_0402_5%  [R_0402]  164.51 91.95 0 bottom
PR1116  0_0402_5%  [R0402_0OHM]  164.51 93.73 0 bottom
PR1117  133K_0402_1%  [R_0402]  168.09 94.17 180 top
PR1119  100K_0402_1%  [R_0402]  164.51 94.61 0 bottom
PR1120  150K_0402_1%  [R_0402]  168.09 95.06 180 top
PR1121  13.3K_0402_1%  [R_0402]  164.89 96.77 0 bottom
PR1122  0_0402_5%  [R0402_0OHM]  165.42 95.5 180 bottom
PR1123  0_0603_5%  [R0603_0OHM]  174.49 95.25 0 bottom
PR1124  10K_0402_1%  [R_0402]  167.57 100.63 90 top
PR1125  4.7_1206_5%  [R_1206]  176.27 100.9 270 bottom
PR1126  3.65K_0603_1%  [R_0603]  166.43 100.14 90 top
PR1128  1_0402_1%  [R_0402]  165.28 100.63 90 top
PR1129  301_0402_1%  [R_0402]  170.3 98.41 270 bottom
PR1130  32.4K_0402_1%  [R_0402]  172.4 95.14 270 top
PR1131  2.61K_0402_1%  [R_0402]  169.35 99.75 180 bottom
PR1132  11K_0402_1%  [R_0402]  169.43 96.67 180 bottom
PR1133  1.47K_0402_1%  [R_0402]  170.29 96.65 0 bottom
PR1134  137K_0402_1%  [R_0402]  172.14 97.5 90 bottom
PR1135  2K_0402_1%  [R_0402]  171.19 97.5 90 bottom
PR1136  562_0402_1%  [R_0402]  168.84 98.69 270 top
PR1137  100_0402_1%  [R_0402]  167.95 98.69 270 top
PR1138  0_0402_5%  [R0402_0OHM]  169.73 96.89 90 top
PR1139  0_0402_5%  [R0402_0OHM]  171.51 96.89 90 top
PR1201  42.2K_0402_1%  [R_0402]  193.1 131.69 90 bottom
PR1202  2.21K_0402_1%  [R_0402]  193.67 142 270 bottom
PR1203  20K_0402_1%  [R_0402]  194.87 132.6 270 bottom
PR1204  1.74K_0402_1%  [R_0402]  192.78 141.08 90 bottom
PR1401  0_0402_5%  [R_0402]  201.81 161.04 180 bottom
PR1402  47K_0402_5%  [R_0402]  200.89 157.48 0 bottom
PR1403  1M_0402_1%  [R_0402]  200.89 158.37 0 bottom
PR1404  4.7_1206_5%  [R_1206]  193.03 158.61 90 bottom
PR1405  0_0603_5%  [R0603_0OHM]  197.67 167.39 90 bottom
PR1406  24.9K_0402_1%  [R_0402]  201.03 163.19 0 bottom
PR1407  10K_0402_5%  [R_0402]  201.81 160.15 180 bottom
PR1408  0_0402_5%  [R_0402]  200.89 161.92 0 bottom
PR1409  1K_0402_1%  [R_0402]  201.03 164.08 0 bottom
PR1410  20K_0402_1%  [R_0402]  202.81 163.18 90 bottom
PU100  TPS51225CRUKR_QFN20_3X3  [TPS51285BRUKR_QFN20_3X3]  42.72 52.26 180 top
PU200  -  [RT8207MZQW_WQFN20_3X3]  61.4 23.05 180 top
PU300  S IC RT8237EZQW(2) WDFN 10P  [TPS51212DSCR_SON10_3X3]  134.68 149.48 270 top
PU400  G971ADJF11U_SO8  [APL5930KAI-TRG_SO8]  39.62 3.94 90 top
PU500  -  [ISL62771HRTZ-T_TQFN40_5X5]  57.56 32.73 0 top
PU600  -  [SY8003DFC_DFN8_2X2]  157.87 42.6 180 bottom
PU703  ISL95520HRZ-T_QFN32_4X4  [ISL95812HRZ-T_QFN32_4X4]  114.92 166.27 90 bottom
PU800  G2992F1U_SO8  [APL5336KAI-TRL_SOP8P8]  30.79 49.23 180 bottom
PU1001  -  [ISL62771HRTZ-T_TQFN40_5X5]  120.36 157.2 180 top
PU1100  -  [ISL62771HRTZ-T_TQFN40_5X5]  167.85 90.08 90 bottom
PU1200  G971ADJF11U_SO8  [APL5930KAI-TRG_SO8]  193.29 139.45 0 bottom
PU1400  -  [SYX198DQNC_QFN10_3X3]  198.24 163.16 90 bottom
Q20  L2N7002LT1G_SOT23-3  [2N7002K_SOT23-3]  59.47 171.58 270 top
Q52  -  [DMN66D0LDW-7_SOT363-6]  53.67 28.26 180 bottom
Q79  DMN63D8LDW_SOT363-6  [DMN66D0LDW-7_SOT363-6]  82.1 63.83 270 top
Q83  -  [2N7002K_SOT23-3]  148.27 106.91 0 top
Q84  -  [2N7002K_SOT23-3]  142.3 104.11 180 bottom
Q87  -  [2N7002K_SOT23-3]  170.91 30.51 180 bottom
Q89  -  [2N7002K_SOT23-3]  174.81 82.83 0 bottom
Q91  -  [2N7002K_SOT23-3]  180.37 85.6 270 top
Q92  -  [2N7002K_SOT23-3]  175.01 30.52 180 bottom
Q93  -  [2N7002K_SOT23-3]  34.85 56.74 180 bottom
Q135  AO3416L_SOT23-3  [AO3416_SOT23-3]  46.79 65.94 0 bottom
Q2407  -  [MMST3904-7-F_SOT323-3]  151.06 45.65 0 bottom
Q2408  -  [MMST3904-7-F_SOT323-3]  139.97 75.1 0 bottom
Q2505  -  [DMN66D0LDW-7_SOT363-6]  162.94 25 90 bottom
Q2507  -  [DMN66D0LDW-7_SOT363-6]  54.24 50.33 0 bottom
Q2509  DMN63D8LDW_SOT363-6  [DMN66D0LDW-7_SOT363-6]  59.69 68.85 270 top
Q2513  AO3416L_SOT23-3  [AO3416_SOT23-3]  48.02 60.58 270 bottom
Q2514  AO3416L_SOT23-3  [AO3416_SOT23-3]  48.02 56.64 270 bottom
Q2515  AO3416L_SOT23-3  [AO3416_SOT23-3]  57.11 55.88 270 bottom
Q2516  -  [DMN66D0LDW-7_SOT363-6]  57.98 48.45 180 bottom
Q6101  DDTA144VCA-7-F-GP  [2N7002K_SOT23-3]  61.63 9.91 90 bottom
Q6102  DDTA144VCA-7-F-GP  [2N7002K_SOT23-3]  61.63 13.97 90 bottom
Q6103  -  [2N7002KW_SOT323-3]  29.9 8.85 0 top
Q6104  DDTA144VCA-7-F-GP  [2N7002K_SOT23-3]  28.89 4.67 0 top
Q6105  -  [2N7002KW_SOT323-3]  30.7 8.13 270 bottom
QA6  -  [DMN66D0LDW-7_SOT363-6]  183.18 21.49 270 bottom
QC1  -  [MESS138W-G_SOT323-3]  104.7 110.93 0 top
QE4  2N7002KW 1N SOT323-3  [2N7002BKW_SOT323-3]  187.85 123.19 90 top
QE5  AP2606AGY-HF 1N SOT26-6  [SI3456BDV-T1-E3_TSOP6]  189.23 125.24 90 top
QH1  -  [SSM3K7002FU_SC70-3]  123.19 109.22 270 top
QM1  DII-DMN65D8LW-7~D  [SSM3K7002FU_SC70-3]  170.94 42.54 270 top
QS2  SI3456BDV-T1-E3 1N TSOP6  [SI3456BDV-T1-E3_TSOP6]  154.6 95.07 180 top
QS3  -  [2N7002KW_SOT323-3]  153.98 98.89 0 top
QV1  DMN66D0LDW-7 2N SOT363-6  [2N7002KDWH_SOT363-6]  177.81 131.89 180 top
QV8  -  [DMN66D0LDW-7_SOT363-6]  182.72 130.78 270 top
QX3  -  [2N7002K_SOT23-3]  25.54 66.04 270 top
QX4  -  [DMN66D0LDW-7_SOT363-6]  27.2 72.39 0 top
QX5  -  [MMBT3904_NL_SOT23-3]  30.03 76.9 90 top
R2  1K_0402_5%  [R_0402]  94.47 88.57 0 bottom
R3  4.7K_0402_5%  [R_0402]  144.58 96.32 90 top
R4  4.7K_0402_5%  [R_0402]  167.01 64.39 180 top
R5  1K_0402_1%  [R_0402]  96.15 64.64 180 top
R6  1K_0402_5%  [R_0402]  122.86 77.08 270 top
R7  4.7K_0402_5%  [R_0402]  167.01 68.07 180 top
R8  1K_0402_1%  [R_0402]  95.23 62.86 0 top
R9  1K_0402_5%  [R_0402]  94.47 84.4 0 bottom
R10  1K_0402_5%  [R_0402]  94.47 79.63 0 bottom
R11  0_0402_5%  [R0402_0OHM]  153.16 68.94 0 bottom
R12  0_0402_5%  [R_0402]  138.07 100.86 90 bottom
R13  1K_0402_5%  [R_0402]  94.47 87.68 0 bottom
R14  1K_0402_5%  [R_0402]  94.47 85.28 0 bottom
R15  1K_0402_5%  [R_0402]  94.47 80.64 0 bottom
R16  1K_0402_5%  [R_0402]  81.58 61.4 0 top
R17  1K_0402_5%  [R_0402]  84.37 65.09 180 top
R18  4.7K_0402_5%  [R_0402]  60.08 70.36 180 top
R19  4.7K_0402_5%  [R_0402]  59.16 73.53 0 top
R20  0_0402_5%  [R_0402]  88.27 76.9 180 bottom
R21  4.7K_0402_5%  [R_0402]  143.62 98.68 0 top
R22  0_0402_5%  [R0402_0OHM]  139.85 101.78 180 bottom
R23  0_0402_5%  [R0402_0OHM]  173.87 52.7 180 top
R24  0_0402_5%  [R0402_0OHM]  173.87 51.82 180 top
R25  0_0402_5%  [R0402_0OHM]  175.11 52.7 0 top
R26  0_0402_5%  [R0402_0OHM]  175.11 51.82 0 top
R27  0_0402_5%  [R0402_0OHM]  195.8 114.74 90 top
R28  0_0402_5%  [R_0402]  196.67 114.74 90 top
R29  0_0402_5%  [R_0402]  196.68 113.85 270 top
R30  100K_0402_5%  [R_0402]  160.39 17.48 270 bottom
R31  1K_0402_5%  [R_0402]  24.17 14.03 0 bottom
R40  15K_0402_5%  [R_0402]  122.99 91.74 90 top
R41  15K_0402_5%  [R_0402]  124.15 91.6 270 top
R42  15K_0402_5%  [R_0402]  122.48 100.91 270 bottom
R44  10K_0402_5%  [R_0402]  160.14 10.97 90 bottom
R49  10K_0402_5%  [R_0402]  45.57 64.64 0 top
R51  10K_0402_5%  [R_0402]  45.57 63.75 0 top
R52  10K_0402_5%  [R_0402]  45.57 65.53 0 top
R53  1K_0402_5%  [R_0402]  40.42 54.23 0 bottom
R54  1K_0402_5%  [R_0402]  46.17 53.77 180 bottom
R55  1K_0402_1%  [R_0402]  125.28 13.77 90 top
R56  1K_0402_1%  [R_0402]  127.56 13.26 90 top
R57  1K_0402_1%  [R_0402]  88.56 23.74 270 top
R59  1K_0402_1%  [R_0402]  86.74 22.82 0 top
R73  1K_0402_1%  [R_0402]  115.8 92.2 0 top
R75  39.2_0402_1%  [R_0402]  121.93 76.16 90 top
R80  300_0402_5%  [R_0402]  94.47 77.6 0 bottom
R82  300_0402_5%  [R_0402]  94.47 78.61 0 bottom
R90  1K_0402_1%  [R_0402]  134.71 100.97 90 bottom
R93  1K_0402_5%  [R_0402]  129.99 75.62 0 top
R96  1K_0402_1%  [R_0402]  135.63 100.96 90 bottom
R106  0_0402_5%  [R_0402]  139.09 92.14 180 bottom
R107  0_0402_5%  [R_0402]  170.22 85.22 0 bottom
R117  1K_0402_5%  [R_0402]  93.02 85.42 270 top
R118  1K_0402_5%  [R_0402]  92.13 85.42 270 top
R119  0_0402_5%  [R0402_0OHM]  151.06 73.86 270 top
R120  1K_0402_5%  [R_0402]  104.58 100.63 90 top
R122  0_0402_5%  [R_0402]  164.78 27.74 90 bottom
R123  0_0402_5%  [R_0402]  165.66 27.74 90 bottom
R124  0_0402_5%  [R_0402]  174.76 71.5 180 top
R125  0_0402_5%  [R_0402]  174.76 70.61 180 top
R126  0_0402_5%  [R_0402]  170.47 28.71 180 bottom
R127  0_0402_5%  [R_0402]  52.51 48.72 270 top
R128  0_0402_5%  [R_0402]  54.08 53.34 0 bottom
R129  0_0402_5%  [R_0402]  53.4 48.72 270 top
R130  0_0402_5%  [R_0402]  55 52.2 180 bottom
R134  1K_0402_5%  [R_0402]  84 82.22 90 top
R135  0_0402_5%  [R_0402]  164.78 30.94 270 bottom
R136  0_0402_5%  [R_0402]  165.66 30.94 270 bottom
R138  0_0603_5%  [R_0603]  168.78 19.05 0 bottom
R139  0_0402_5%  [R_0402]  174.8 23.12 180 bottom
R140  0_0402_5%  [R_0402]  173.88 25.09 0 bottom
R141  0_0402_5%  [R_0402]  173.88 24.17 0 bottom
R142  0_0402_5%  [R_0402]  175.65 24.18 0 bottom
R143  0_0402_5%  [R_0402]  175.66 25.08 0 bottom
R144  0_0402_5%  [R_0402]  165.54 30.02 90 top
R145  0_0402_5%  [R_0402]  164.65 30.02 90 top
R146  0_0402_5%  [R_0402]  173.92 28.19 0 bottom
R147  0_0402_5%  [R_0402]  175.68 22.4 90 bottom
R148  0_0402_5%  [R_0402]  167.77 21.32 270 bottom
R149  0_0603_5%  [R_0603]  172.71 20.83 180 bottom
R150  0_0402_5%  [R_0402]  173.48 29.68 180 bottom
R151  0_0603_5%  [R_0603]  163.57 18.35 270 bottom
R152  0_0603_5%  [R_0603]  173.86 19.56 0 bottom
R153  0_0402_5%  [R0402_0OHM]  166.67 30.73 0 bottom
R154  1K_0402_5%  [R_0402]  104.96 99.33 270 top
R155  1K_0402_5%  [R_0402]  105.47 100.63 90 top
